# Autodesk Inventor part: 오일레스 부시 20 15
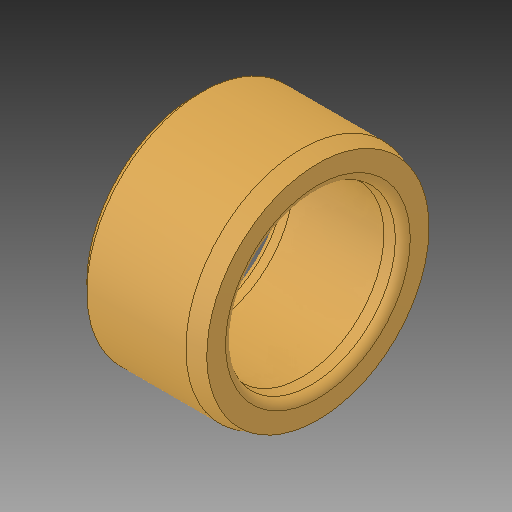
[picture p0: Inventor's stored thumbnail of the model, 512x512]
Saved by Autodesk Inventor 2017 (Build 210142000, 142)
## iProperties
Created: 2024-08
Part Number: 오일레스 부시 20 15
Material: 일반
Document SubType Name: Modeling
Designer: MRC
Density: 1 g/cm^3
Appearance: 기본값
Author: jhkim
Sending System: Autodesk Inventor 2025
Preprocessor: ST-DEVELOPER v20
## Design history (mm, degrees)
feature "솔리드1"
node "솔리드2"
